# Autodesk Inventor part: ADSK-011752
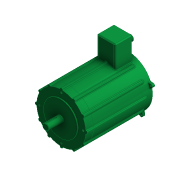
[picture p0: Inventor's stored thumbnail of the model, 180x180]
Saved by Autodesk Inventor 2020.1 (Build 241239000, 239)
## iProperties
Created: 2000-02
Part Number: ADSK-011752
Material: Pearson HRS
Document SubType Name: Modeling
Designer: mpflueger
Density: 7.83 g/cm^3
Appearance: Green(Flat)
Mass: 42660.8 g
Surface Area: 2028.87 cm^2
Volume: 5448.38 cm^3
Control State: 0
Master: False
Checked Out: False
Shininess: 20.0
Length Units: 11269
Angle Units: 11279
Time Units: 11290
Mass Units: 11283
Length Display Precision: 3
Angle Display Precision: 2
Compacted: True
Dimensions: 243,1x300,6x183,1 mm
Mass: 42,661 kg
DocNumber: ADSK-011752.ipt
Folder: 01 - Themengebiete\Simplification\01 - Packaging machine\
VDS_Category: 3D Komponenten
VLT_Material: Pearson HRS
Density: 0.0
Volumn: 0.0
Area: 0.0
PropertySet Name: Model Information
Author: mpflueger
Revision Number: -
Title: engine
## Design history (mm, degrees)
pattern_circular "Circular Pattern1" dims angle "d47" = 360 deg
pattern_circular "Circular Pattern4" dims angle "d70" = 360 deg
node "Solide1"
  node "Extrusion1" dims "d1" = 50, "d2" = 0
  node "Extrusion2" dims "d4" = 3, "d5" = 0
  node "Extrusion3" dims "d7" = 225, "d8" = 0
  node "Hole1" dims "d26" = 6.647, "d27" = 9.525, "d28" = 6.35, "d29" = 60 deg, "d30" = 22.2, "d31" = 118 deg, "d102" = 16
  node "Extrusion4" dims "d13" = 2.5, "d14" = 0
  node "Extrusion5" dims "d20" = 2.6416, "d21" = 0
  node "Chamfer1" dims "d32" = 1, "d33" = 1, "d98" = 45 deg
  node "Chamfer2" dims "d34" = 1, "d35" = 25, "d99" = 45 deg
sketch "Sketch1"
  geometry: C1 r 11 at (0, 0); 1 further point
  constraints: 1 centre point, 1 coincident
  dimensions: "d0" = 22 diameter of C1
sketch "Sketch2"
  geometry: C1 r 11 at (0, 0) reference; C2 r 57 at (0, 0)
  constraints: 1 centre point, 1 coincident
  dimensions: "d3" = 114 diameter of C2
sketch "Sketch3"
  geometry: C1 r 84 at (0, 0); C2 r 11 at (0, 0) reference
  constraints: 1 centre point, 1 concentric
  dimensions: "d6" = 168 diameter of C1
sketch "Sketch14"
  geometry: C1 r 10 at (26.477, -34.4); 1 further point
  constraints: 1 centre point, 1 vertical alignment
  dimensions: "d95" = 20 diameter of C1; "d108" = 118 distance of point (26.477, -152.4) C1.centre
extrude "Extrusion10" join sketch "Sketch14" distance "d96" = 25; taper "d97" = 0 deg
sketch "Sketch11"
  geometry: C1 r 61 at (0, 0); A1 r 84 centre (0, 0) between (75.958, 35.867) and (10.639, 83.324) reference
  constraints: 1 centre point, 1 coincident
  dimensions: "d104" = 122 diameter of C1
extrude "Extrusion8" join sketch "Sketch11" distance "d77" = 5; taper "d78" = 0 deg
sketch "Sketch12"
  geometry: C1 r 11 at (0, 0) reference
extrude "Extrusion9" join sketch "Sketch12" distance "d79" = 17.6022; taper "d80" = 0 deg
chamfer "Chamfer4" distance "d81" = 3; stored, may be unused: second distance "d82" = 3, angle "d100" = 45 deg
fillet "Fillet8" dims "d83" = 5
fillet "Fillet9" dims "d84" = 3
sketch "Sketch13"
  geometry: A1 r 5 centre (0, 91) between (4.532, 93.113) and (-4.532, 93.113) reference
hole "Hole4" sketch "Sketch13" diameter "d89" = 5.35; stored, may be unused: countersink angle "d92" = 60 deg, drill point angle "d94" = 118 deg; dims "d90" = 9.525, "d91" = 6.35, "d93" = 19.05, "d103" = 12
sketch "Sketch7"
  geometry: L1 (57, 0)-(-57, 0) reference; L2 (-4, 0)-(-4, -200); L3 (4, -200)-(4, 0); L4 (84, -225)-(-84, -225) reference; L5 (0, 108.6)-(0, -280.6) reference; A1 r 4 centre (0, -200) between (-4, -200) and (4, -200)
  constraints: 4 end point, 2 point on circle, 2 point on line, 2 tangent, 1 centre point, 1 parallel, 1 perpendicular
  dimensions: "d38" = 8 distance between parallel lines of L2 L3; "d39" = 4 distance between parallel lines of L2 L5 (= 0.5 x d38); "d40" = 200 vertical distance of A1.centre L2.start
extrude "Extrusion6" join sketch "Sketch7" stored distance "d41" = 8; taper "d42" = 0 deg
fillet "Fillet2" dims "d43" = 3
chamfer "Chamfer3" distance "d51" = 3; stored, may be unused: second distance "d52" = 3, angle "d101" = 45 deg
sketch "Sketch8"
  geometry: L1 (4.532, 93.113)-(9.007, 83.516); L2 (-4.532, 93.113)-(-9.007, 83.516); L3 (0, 91)-(0, 84); A1 r 84 centre (0, 0) between (9.007, 83.516) and (-9.007, 83.516) reference; A2 r 5 centre (0, 91) between (4.532, 93.113) and (-4.532, 93.113)
  constraints: 6 end point, 5 point on circle, 2 tangent, 1 centre point, 1 equal length, 1 vertical, 1 other
  dimensions: "d105" = 91 distance of L3.start A1.centre; "d106" = 5 radius of A2; "d107" = 50 deg angle of L2 L1
extrude "Extrusion7" join sketch "Sketch8" distance "d53" = 8; taper "d54" = 0 deg
fillet "Fillet7" dims "d55" = 3
workplane "Work Plane2"
sketch "Sketch4"
  geometry: L1 (-11, 0)-(-11, -50) reference; L2 (11, 0)-(11, -50) reference; L3 (-2.5, 0)-(2.5, 0); L4 (2.5, 0)-(2.5, -35); L5 (-2.5, -35)-(-2.5, 0); L6 (0, 0)-(0, -15.261); A1 r 2.5 centre (0, -35) between (-2.5, -35) and (2.5, -35); 1 further point
  constraints: 8 end point, 2 midpoint, 2 parallel, 2 point on circle, 2 tangent, 1 centre point, 1 horizontal, 1 perpendicular, 1 point on line
  dimensions: "d11" = 5 distance between parallel lines of L5 L4; "d12" = 35 distance from line of A1.centre L3
workplane "Work Plane3"
sketch "Sketch5"
  geometry: L1 (-31.5, -205)-(31.5, -205); L2 (31.5, -205)-(31.5, -263); L3 (31.5, -263)-(-31.5, -263); L4 (-31.5, -263)-(-31.5, -205); L5 (84, -53)-(-84, -53) reference; 1 further point
  constraints: 8 end point, 2 parallel, 1 horizontal, 1 perpendicular
  dimensions: "d16" = 152 distance between parallel lines of L1 L5; "d17" = 31.5 distance from line of L4 point (0, 0) (= 0.5 x d18); "d18" = 63 distance of L1.start L1.end; "d19" = 58 distance between parallel lines of L3 L1
sketch "Sketch6"
  geometry: C1 r 57 at (0, 0) reference; C2 r 11 at (0, 0) reference; A1 r 74 centre (0, 0) between (-74, 0) and (74, 0); 2 further points
  constraints: 4 point on circle, 2 horizontal alignment, 2 vertical alignment, 1 centre point, 1 coincident, 1 concentric
  dimensions: "d22" = 148 diameter of A1
workplane "Work Plane4"
workaxis "Work Axis1"
node "Corps solides"
node "Corps surfaciques"
other parameters: "d15" = 155
